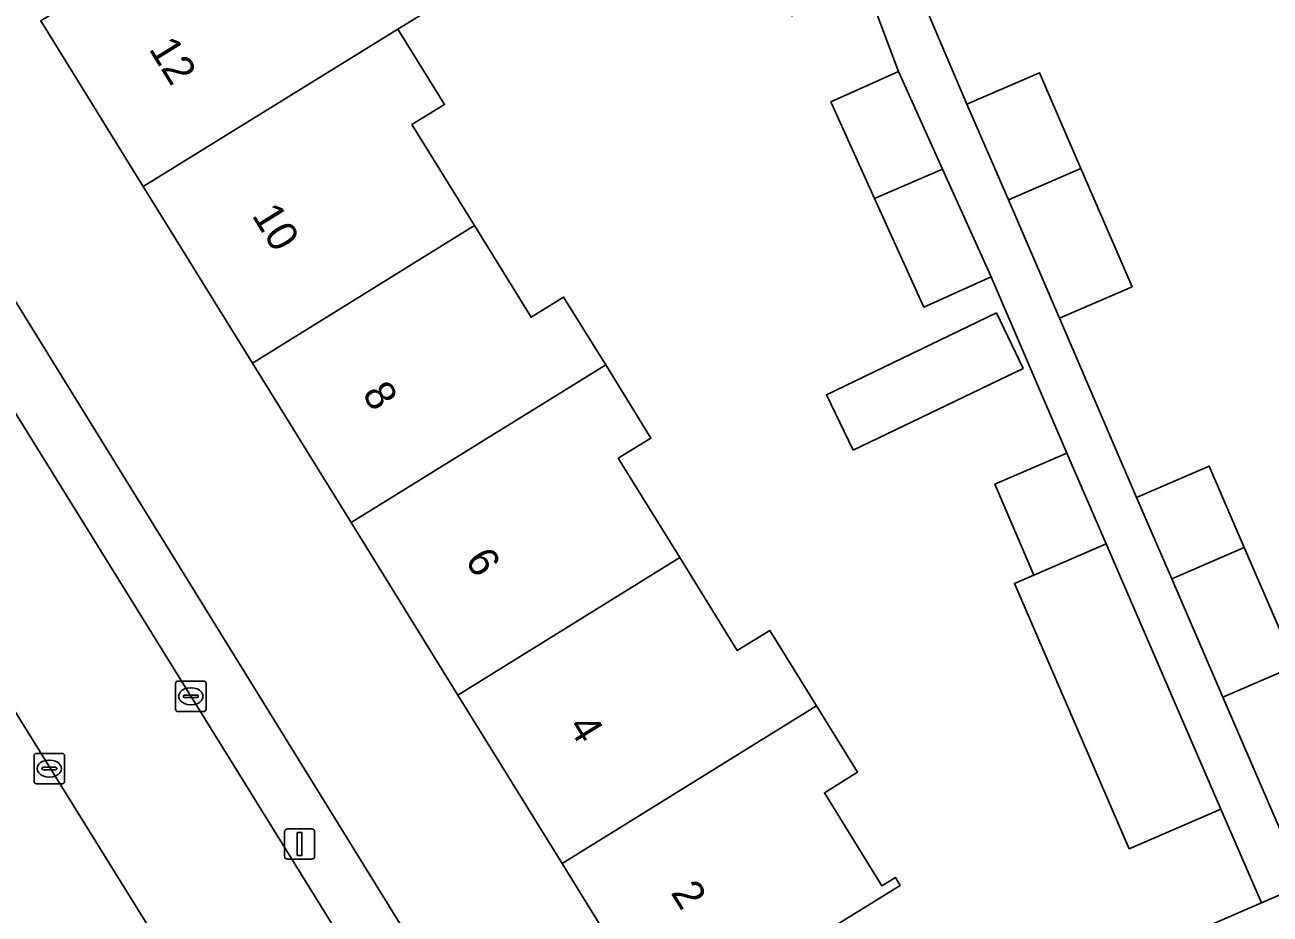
# Model space of a CAD drawing. Extents: x 159352 to 160617, y 385888 to 387323.
# Drawn here: x 159529.07 to 159569.99, y 386171.6 to 386200.82 of the extents above; entities that cross this region are included whole.
import ezdxf

# ---------------------------------------------------------------- set-up
doc = ezdxf.new("R2010")
doc.units = 0
for name, color, linetype in [('IMGEO_Berm_groen', 7, 'Continuous'), ('IMGEO_Erf', 7, 'Continuous'), ('IMGEO_Kolk', 7, 'Continuous'), ('IMGEO_Lichtmast', 7, 'Continuous'), ('IMGEO_Pand', 7, 'Continuous'), ('IMGEO_Pand_nummerreeks', 7, 'Continuous'), ('IMGEO_Rijbaan_lokaal_open', 7, 'Continuous'), ('IMGEO_Voetpad_open', 7, 'Continuous')]:
    doc.layers.add(name, color=color, linetype=linetype)

msp = doc.modelspace()

# ---------------------------------------------------------------- linework, layer by layer
at = {"layer": 'IMGEO_Berm_groen'}
msp.add_lwpolyline([(159539.198, 386161.413), (159512.438, 386204.54)], dxfattribs=at)
at = {"layer": 'IMGEO_Erf'}
for points in [[(159555.559, 386198.293), (159557.775, 386199.294), (159556.696, 386202.183), (159554.277, 386201.118), (159553.131, 386203.721), (159551.683, 386207.012), (159550.235, 386210.304), (159552.654, 386211.368), (159550.47, 386216.811), (159548.082, 386215.78), (159546.622, 386219.159), (159545.151, 386222.565), (159547.595, 386223.466), (159545.705, 386227.831), (159517.863, 386215.778)], [(159516.528, 386211.509), (159545.289, 386164.985)], [(159543.251, 386201.877), (159541.325, 386200.685), (159542.858, 386198.207), (159541.786, 386197.543), (159543.84, 386194.224), (159545.702, 386191.217), (159546.773, 386191.88), (159548.154, 386189.648), (159549.641, 386187.246), (159548.569, 386186.582), (159550.589, 386183.319), (159552.479, 386180.264), (159553.55, 386180.927), (159553.803, 386180.519), (159555.087, 386178.444), (159556.434, 386176.267), (159555.342, 386175.591), (159557.234, 386172.533), (159557.674, 386172.805), (159557.836, 386172.545), (159549.621, 386167.462)], [(159558.706, 386201.31), (159560.028, 386198.213), (159562.413, 386199.245), (159563.774, 386196.099), (159565.454, 386192.216), (159563.068, 386191.184), (159565.599, 386185.292), (159567.984, 386186.324), (159569.143, 386183.644), (159570.823, 386179.761), (159568.437, 386178.729), (159571.098, 386172.573)], [(159549.968, 386168.013), (159546.719, 386173.264), (159543.292, 386178.802), (159539.786, 386184.469), (159536.545, 386189.708), (159532.957, 386195.506), (159529.585, 386200.956)], [(159550.156, 386163.506), (159569.705, 386171.97), (159568.371, 386175.051), (159565.36, 386173.749), (159561.589, 386182.468), (159562.231, 386182.745), (159560.94, 386185.728), (159563.311, 386186.754), (159560.825, 386192.547), (159558.609, 386191.545), (159556.994, 386195.118), (159555.559, 386198.293)]]:
    msp.add_lwpolyline(points, dxfattribs=at)
msp.add_lwpolyline([(159560.998, 386191.355), (159561.874, 386189.535), (159556.291, 386186.848), (159555.415, 386188.668)], close=True, dxfattribs=at)
at = {"layer": 'IMGEO_Kolk'}
for p, q in [((159534.018, 386178.333), (159534.018, 386179.185)), ((159534.093, 386179.259), (159534.945, 386179.259)), ((159535.019, 386179.185), (159535.019, 386178.333)), ((159534.32, 386178.802), (159534.718, 386178.802)), ((159534.506, 386179.039), (159534.531, 386179.039)), ((159534.277, 386178.753), (159534.277, 386178.765)), ((159534.715, 386178.716), (159534.317, 386178.716)), ((159534.529, 386178.479), (159534.504, 386178.479)), ((159534.761, 386178.765), (159534.761, 386178.753)), ((159534.945, 386178.259), (159534.093, 386178.259)), ((159529.368, 386175.959), (159529.368, 386176.811)), ((159529.443, 386176.885), (159530.295, 386176.885)), ((159530.369, 386176.811), (159530.369, 386175.959)), ((159529.627, 386176.379), (159529.627, 386176.391)), ((159530.065, 386176.342), (159529.667, 386176.342)), ((159529.67, 386176.428), (159530.068, 386176.428)), ((159529.856, 386176.665), (159529.881, 386176.665)), ((159530.111, 386176.391), (159530.111, 386176.379)), ((159529.879, 386176.105), (159529.854, 386176.105)), ((159530.295, 386175.885), (159529.443, 386175.885))]:
    msp.add_line(p, q, dxfattribs=at)
for points in [[(159534.018, 386178.333), (159534.018, 386179.185)], [(159534.093, 386179.259), (159534.945, 386179.259)], [(159535.019, 386179.185), (159535.019, 386178.333)], [(159534.945, 386178.259), (159534.093, 386178.259)], [(159529.368, 386175.959), (159529.368, 386176.811)], [(159529.443, 386176.885), (159530.295, 386176.885)], [(159530.369, 386176.811), (159530.369, 386175.959)], [(159530.295, 386175.885), (159529.443, 386175.885)]]:
    msp.add_lwpolyline(points, dxfattribs=at)
for centre, radius, start, end in [((159534.095, 386179.183), 0.0765, 91.552, 178.448), ((159534.095, 386179.183), 0.0765, 91.552, 178.448), ((159534.943, 386179.183), 0.0765, 1.552, 88.448), ((159534.943, 386179.183), 0.0765, 1.552, 88.448), ((159534.317, 386178.762), 0.0403, 85.8775, 175.7526), ((159534.722, 386178.764), 0.0386, 1.7309, 96.639), ((159534.314, 386178.752), 0.0366, 178.938, 274.7102), ((159534.718, 386178.759), 0.043, 264.8664, 352.4533), ((159534.095, 386178.335), 0.0765, 181.552, 268.448), ((159534.095, 386178.335), 0.0765, 181.552, 268.448), ((159534.943, 386178.335), 0.0765, 271.552, 358.448), ((159534.943, 386178.335), 0.0765, 271.552, 358.448), ((159529.445, 386176.809), 0.0765, 91.552, 178.448), ((159529.445, 386176.809), 0.0765, 91.552, 178.448), ((159530.293, 386176.809), 0.0765, 1.552, 88.448), ((159530.293, 386176.809), 0.0765, 1.552, 88.448), ((159529.667, 386176.388), 0.0403, 85.8775, 175.7526), ((159529.664, 386176.378), 0.0366, 178.938, 274.7102), ((159530.068, 386176.385), 0.043, 264.8664, 352.4533), ((159530.072, 386176.39), 0.0386, 1.7309, 96.639), ((159529.445, 386175.961), 0.0765, 181.552, 268.448), ((159529.445, 386175.961), 0.0765, 181.552, 268.448), ((159530.293, 386175.961), 0.0765, 271.552, 358.448), ((159530.293, 386175.961), 0.0765, 271.552, 358.448)]:
    msp.add_arc(centre, radius, start, end, dxfattribs=at)
for centre, major_axis, ratio, start_param, end_param in [((159534.505, 386178.759), (-0.387, 0.002), 0.722429, 4.712389, 7.853982), ((159534.53, 386178.759), (-0.39, 0.002), 0.717154, 1.570796, 4.712389), ((159529.855, 386176.385), (-0.387, 0.002), 0.722429, 4.712389, 7.853982), ((159529.88, 386176.385), (-0.39, 0.002), 0.717154, 1.570796, 4.712389)]:
    msp.add_ellipse(centre, major_axis=major_axis, ratio=ratio, start_param=start_param, end_param=end_param, dxfattribs=at)
at = {"layer": 'IMGEO_Lichtmast'}
for p, q in [((159537.599, 386173.506), (159537.599, 386174.306)), ((159537.599, 386174.306), (159537.599, 386173.506)), ((159537.699, 386174.406), (159538.489, 386174.406)), ((159538.489, 386174.406), (159537.699, 386174.406)), ((159538.589, 386174.306), (159538.589, 386173.506)), ((159538.589, 386173.506), (159538.589, 386174.306)), ((159538.489, 386173.406), (159537.699, 386173.406)), ((159537.699, 386173.406), (159538.489, 386173.406))]:
    msp.add_line(p, q, dxfattribs=at)
msp.add_lwpolyline([(159538.019, 386174.281), (159538.169, 386174.281), (159538.169, 386173.531), (159538.019, 386173.531), (159538.019, 386174.281)], dxfattribs=at)
for centre, start, end in [((159537.699, 386174.306), 90, 180), ((159537.699, 386174.306), 90, 180), ((159538.489, 386174.306), 0, 90), ((159538.489, 386174.306), 360, 90), ((159537.699, 386173.506), 180, 270), ((159537.699, 386173.506), 180, 270), ((159538.489, 386173.506), 270, 0), ((159538.489, 386173.506), 270, 0)]:
    msp.add_arc(centre, 0.1, start, end, dxfattribs=at)
at = {"layer": 'IMGEO_Pand'}
for points in [[(159538.814, 386206.667), (159536.881, 386205.471), (159529.585, 386200.956), (159532.957, 386195.506), (159541.325, 386200.685), (159543.251, 386201.877), (159541.953, 386203.973), (159540.889, 386203.314)], [(159532.957, 386195.506), (159536.545, 386189.708), (159543.84, 386194.224), (159541.786, 386197.543), (159542.858, 386198.207), (159541.325, 386200.685)], [(159559.227, 386196.082), (159557.775, 386199.294), (159555.559, 386198.293), (159556.994, 386195.118)], [(159563.774, 386196.099), (159562.413, 386199.245), (159560.028, 386198.213), (159561.388, 386195.07)], [(159556.994, 386195.118), (159558.609, 386191.545), (159560.825, 386192.547), (159559.227, 386196.082)], [(159561.388, 386195.07), (159563.068, 386191.184), (159565.454, 386192.216), (159563.774, 386196.099)], [(159536.545, 386189.708), (159539.786, 386184.469), (159548.154, 386189.648), (159546.773, 386191.88), (159545.702, 386191.217), (159543.84, 386194.224)], [(159556.291, 386186.848), (159561.874, 386189.535), (159560.998, 386191.355), (159555.415, 386188.668)], [(159550.589, 386183.319), (159548.569, 386186.582), (159549.641, 386187.246), (159548.154, 386189.648), (159539.786, 386184.469), (159543.292, 386178.802)], [(159564.603, 386183.765), (159563.311, 386186.754), (159560.94, 386185.728), (159562.231, 386182.745)], [(159569.143, 386183.644), (159567.984, 386186.324), (159565.599, 386185.292), (159566.757, 386182.615)], [(159562.231, 386182.745), (159561.589, 386182.468), (159565.36, 386173.749), (159568.371, 386175.051), (159564.603, 386183.765)], [(159543.292, 386178.802), (159546.719, 386173.264), (159555.087, 386178.444), (159553.803, 386180.519), (159553.55, 386180.927), (159552.479, 386180.264), (159550.589, 386183.319)], [(159566.757, 386182.615), (159568.437, 386178.729), (159570.823, 386179.761), (159569.143, 386183.644)], [(159546.719, 386173.264), (159549.968, 386168.013), (159549.471, 386167.706), (159549.621, 386167.462), (159557.836, 386172.545), (159557.674, 386172.805), (159557.234, 386172.533), (159555.342, 386175.591), (159556.434, 386176.267), (159555.087, 386178.444)]]:
    msp.add_lwpolyline(points, close=True, dxfattribs=at)
at = {"layer": 'IMGEO_Rijbaan_lokaal_open'}
msp.add_lwpolyline([(159507.467, 386212.616), (159508.214, 386211.406), (159511.141, 386206.664), (159512.438, 386204.54), (159539.198, 386161.413), (159543.479, 386164.305), (159528.036, 386189.214), (159514.607, 386210.815)], dxfattribs=at)
at = {"layer": 'IMGEO_Voetpad_open'}
for points in [[(159514.607, 386210.815), (159528.036, 386189.214), (159543.479, 386164.305), (159545.289, 386164.985), (159516.528, 386211.509)], [(159556.696, 386202.183), (159557.775, 386199.294), (159559.227, 386196.082), (159560.825, 386192.547), (159563.311, 386186.754), (159564.603, 386183.765), (159568.371, 386175.051), (159569.705, 386171.97), (159571.098, 386172.573), (159568.437, 386178.729), (159566.757, 386182.615), (159565.599, 386185.292), (159563.068, 386191.184), (159561.388, 386195.07), (159560.028, 386198.213), (159558.706, 386201.31)], [(159590.345, 386180.906), (159571.098, 386172.573), (159569.705, 386171.97), (159550.156, 386163.506)]]:
    msp.add_lwpolyline(points, dxfattribs=at)

# ---------------------------------------------------------------- texts
at = {"layer": 'IMGEO_Pand_nummerreeks'}
for s, rotation, p in [('12', 301.7474, (159533.119, 386200.033)), ('10', 301.7464, (159536.504, 386194.562)), ('8', 301.7464, (159540.13, 386188.703)), ('6', 301.7464, (159543.51, 386183.239)), ('4', 301.7464, (159546.893, 386177.773)), ('2', 301.7464, (159550.274, 386172.308))]:
    msp.add_text(s, height=1, rotation=rotation, dxfattribs=at).set_placement(p)

doc.saveas('drawing.dxf')
